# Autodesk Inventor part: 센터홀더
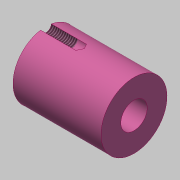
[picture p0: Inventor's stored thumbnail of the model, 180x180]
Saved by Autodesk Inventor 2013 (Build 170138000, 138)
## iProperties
Created: 2019-10
Part Number: 센터홀더
Material: 강철, 연강
Document SubType Name: Modeling
Designer: mduedu
Density: 1 g/cm^3
Author: mduedu
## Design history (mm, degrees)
sketch "스케치1"
  geometry: L1 (0, 0)-(20, 0); L2 (12, -3)-(20, -3); L3 (20, -3)-(20, -7.5); L4 (20, -7.5)-(0, -7.5); L5 (0, -7.5)-(0, -4.127); L6 (0, -4.127)-(12, -3.751); L7 (12, -3.751)-(12, -3)
  constraints: 14 end point, 2 horizontal, 2 parallel, 2 perpendicular, 2 vertical alignment
  dimensions: "d0" = 20 distance of L1.start L1.end; "d1" = 6 diameter of L2 L1; "d2" = 12 distance between parallel lines of L5 L7; "d3" = 7.502 diameter of L6.end L1; "d4" = 8.254 diameter of L5.end L1; "d5" = 15 diameter of L4 L1
revolve "회전1" sketch "스케치1" stored, may be unused: angle "d6" = 90 deg
sketch "스케치2"
  geometry: 3 further points
  constraints: 2 vertical alignment, 1 other
hole "구멍1" sketch "스케치2" at (0, 7.5) diameter "d7" = 2.459; stored, may be unused: countersink angle "d11" = 90 deg, drill point angle "d13" = 118 deg; dims "d8" = 6, "d9" = 4, "d10" = 2, "d12" = 8
node "솔리드1"
